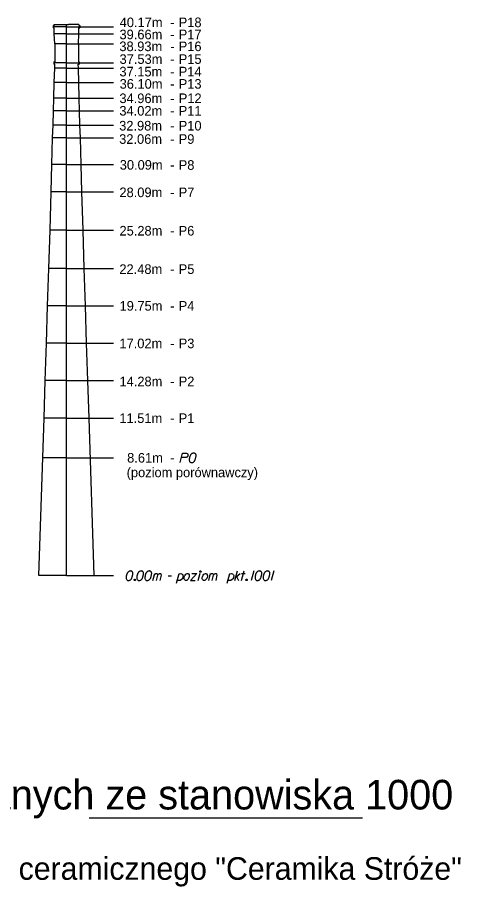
# Model space of a CAD drawing. Extents: x 138 to 264, y -75 to 121.
# Drawn here: x 182.42 to 189.53, y 85.34 to 99.29 of the extents above; entities that cross this region are included whole.
import ezdxf

# ---------------------------------------------------------------- set-up
doc = ezdxf.new("R2010")
doc.units = 0
doc.layers.add('Opisy', color=7, linetype='Continuous')

msp = doc.modelspace()

# ---------------------------------------------------------------- linework, layer by layer
at = {"layer": 'Opisy'}
for p, q in [((182.991, 99.16), (182.991, 99.141)), ((183.008, 99.16), (182.991, 99.16)), ((183.204, 99.141), (182.991, 99.141)), ((182.991, 99.141), (182.991, 99.122)), ((183.008, 99.122), (182.991, 99.122)), ((183.008, 99.178), (183.008, 99.16)), ((183.008, 99.178), (183.234, 99.178)), ((183.008, 99.028), (183.008, 99.122)), ((183.204, 90.332), (183.204, 99.178)), ((183.204, 99.141), (183.957, 99.141)), ((183.4, 99.178), (183.234, 99.178)), ((183.4, 99.178), (183.4, 99.16)), ((183.4, 99.16), (183.417, 99.16)), ((183.4, 99.122), (183.417, 99.122)), ((183.4, 99.028), (183.4, 99.122)), ((183.417, 99.16), (183.417, 99.141)), ((183.417, 99.141), (183.417, 99.122)), ((183.204, 99.028), (183.008, 99.028)), ((183.014, 98.868), (183.008, 99.028)), ((183.204, 99.028), (183.957, 99.028)), ((183.394, 98.868), (183.4, 99.028)), ((183.204, 98.868), (183.014, 98.868)), ((183.014, 98.868), (183.014, 98.58)), ((183.204, 98.868), (183.957, 98.868)), ((183.394, 98.868), (183.394, 98.58)), ((183.001, 98.58), (183.001, 98.561)), ((183.001, 98.58), (183.014, 98.58)), ((183.204, 98.561), (183.001, 98.561)), ((183.001, 98.561), (183.001, 98.542)), ((183.016, 98.542), (183.001, 98.542)), ((183.014, 98.478), (183.016, 98.542)), ((183.204, 98.561), (183.957, 98.561)), ((183.394, 98.478), (183.392, 98.542)), ((183.392, 98.542), (183.407, 98.542)), ((183.407, 98.58), (183.394, 98.58)), ((183.407, 98.58), (183.407, 98.561)), ((183.407, 98.561), (183.407, 98.542)), ((183.008, 98.247), (183.014, 98.478)), ((183.204, 98.478), (183.014, 98.478)), ((183.204, 98.478), (183.957, 98.478)), ((183.4, 98.247), (183.394, 98.478)), ((183.001, 97.997), (183.008, 98.247)), ((183.204, 98.247), (183.008, 98.247)), ((183.204, 98.247), (183.957, 98.247)), ((183.407, 97.997), (183.4, 98.247)), ((182.994, 97.791), (183.001, 97.997)), ((183.204, 97.997), (183.001, 97.997)), ((183.204, 97.997), (183.957, 97.997)), ((183.413, 97.791), (183.407, 97.997)), ((182.989, 97.563), (182.994, 97.791)), ((183.204, 97.791), (182.994, 97.791)), ((183.204, 97.791), (183.957, 97.791)), ((183.419, 97.563), (183.413, 97.791)), ((182.981, 97.361), (182.989, 97.563)), ((183.204, 97.563), (182.989, 97.563)), ((183.204, 97.563), (183.957, 97.563)), ((183.426, 97.361), (183.419, 97.563)), ((182.969, 96.929), (182.981, 97.361)), ((183.204, 97.361), (182.981, 97.361)), ((183.204, 97.361), (183.957, 97.361)), ((183.438, 96.929), (183.426, 97.361)), ((182.956, 96.491), (182.969, 96.929)), ((183.204, 96.929), (182.969, 96.929)), ((183.204, 96.929), (183.957, 96.929)), ((183.452, 96.491), (183.438, 96.929)), ((182.939, 95.874), (182.956, 96.491)), ((183.204, 96.491), (182.956, 96.491)), ((183.204, 96.491), (183.957, 96.491)), ((183.469, 95.874), (183.452, 96.491)), ((182.919, 95.261), (182.939, 95.874)), ((183.204, 95.874), (182.939, 95.874)), ((183.204, 95.874), (183.957, 95.874)), ((183.489, 95.261), (183.469, 95.874)), ((182.9, 94.662), (182.919, 95.261)), ((183.204, 95.261), (182.919, 95.261)), ((183.204, 95.261), (183.957, 95.261)), ((183.508, 94.662), (183.489, 95.261)), ((182.882, 94.064), (182.9, 94.662)), ((183.204, 94.662), (182.9, 94.662)), ((183.204, 94.662), (183.957, 94.662)), ((183.526, 94.064), (183.508, 94.662)), ((182.863, 93.462), (182.882, 94.064)), ((183.204, 94.064), (182.882, 94.064)), ((183.204, 94.064), (183.957, 94.064)), ((183.545, 93.462), (183.526, 94.064)), ((182.843, 92.856), (182.863, 93.462)), ((183.204, 93.462), (182.863, 93.462)), ((183.204, 93.462), (183.957, 93.462)), ((183.565, 92.856), (183.545, 93.462)), ((182.761, 90.332), (182.843, 92.856)), ((183.204, 92.856), (182.843, 92.856)), ((183.204, 92.856), (183.957, 92.856)), ((183.647, 90.332), (183.565, 92.856)), ((183.204, 92.219), (182.822, 92.219)), ((183.204, 92.219), (183.957, 92.219)), ((183.204, 90.332), (182.761, 90.332)), ((183.204, 90.332), (183.957, 90.332)), ((183.569, 86.444), (187.953, 86.444))]:
    msp.add_line(p, q, dxfattribs=at)
for points in [[(185.026, 92.145), (185.067, 92.299), (185.12, 92.299), (185.127, 92.298), (185.13, 92.296), (185.138, 92.293), (185.143, 92.289), (185.146, 92.284), (185.15, 92.278), (185.152, 92.27), (185.154, 92.262), (185.152, 92.256), (185.151, 92.251), (185.149, 92.247), (185.146, 92.243), (185.143, 92.238), (185.138, 92.234), (185.134, 92.232), (185.128, 92.23), (185.122, 92.228), (185.049, 92.228)], [(185.247, 92.299), (185.245, 92.299), (185.237, 92.298), (185.232, 92.296), (185.229, 92.295), (185.223, 92.293), (185.215, 92.289), (185.209, 92.285), (185.203, 92.281), (185.2, 92.276), (185.196, 92.27), (185.192, 92.264), (185.189, 92.256), (185.186, 92.251), (185.184, 92.244), (185.18, 92.232), (185.177, 92.214), (185.174, 92.199), (185.174, 92.186), (185.175, 92.176), (185.18, 92.165), (185.184, 92.159), (185.19, 92.152), (185.197, 92.147), (185.201, 92.146), (185.208, 92.145), (185.214, 92.145), (185.224, 92.146), (185.232, 92.148), (185.239, 92.152), (185.247, 92.158), (185.251, 92.162), (185.256, 92.166), (185.259, 92.171), (185.262, 92.175), (185.264, 92.181), (185.265, 92.183), (185.268, 92.19), (185.27, 92.197), (185.272, 92.204), (185.274, 92.209), (185.275, 92.213), (185.276, 92.217), (185.279, 92.228), (185.28, 92.234), (185.281, 92.24), (185.282, 92.249), (185.283, 92.26), (185.283, 92.264), (185.282, 92.268), (185.281, 92.273), (185.277, 92.281), (185.274, 92.285), (185.27, 92.289), (185.265, 92.293), (185.26, 92.295), (185.257, 92.296), (185.253, 92.298), (185.247, 92.299)], [(184.233, 90.406), (184.231, 90.406), (184.223, 90.405), (184.219, 90.404), (184.215, 90.403), (184.209, 90.4), (184.202, 90.397), (184.196, 90.393), (184.189, 90.388), (184.186, 90.383), (184.182, 90.377), (184.179, 90.371), (184.175, 90.364), (184.172, 90.359), (184.17, 90.352), (184.166, 90.34), (184.163, 90.321), (184.16, 90.307), (184.16, 90.293), (184.162, 90.284), (184.166, 90.273), (184.17, 90.267), (184.176, 90.259), (184.183, 90.255), (184.187, 90.253), (184.194, 90.252), (184.2, 90.252), (184.21, 90.253), (184.219, 90.256), (184.225, 90.259), (184.233, 90.266), (184.237, 90.269), (184.242, 90.274), (184.245, 90.279), (184.248, 90.283), (184.25, 90.289), (184.251, 90.291), (184.254, 90.297), (184.256, 90.304), (184.259, 90.312), (184.26, 90.317), (184.261, 90.32), (184.262, 90.325), (184.265, 90.336), (184.266, 90.342), (184.267, 90.348), (184.268, 90.357), (184.27, 90.367), (184.27, 90.371), (184.268, 90.376), (184.267, 90.381), (184.263, 90.388), (184.26, 90.393), (184.256, 90.397), (184.251, 90.4), (184.246, 90.403), (184.243, 90.404), (184.239, 90.405), (184.233, 90.406)], [(184.404, 90.406), (184.402, 90.406), (184.395, 90.405), (184.39, 90.404), (184.386, 90.403), (184.38, 90.4), (184.373, 90.397), (184.367, 90.393), (184.361, 90.388), (184.357, 90.383), (184.353, 90.377), (184.35, 90.371), (184.346, 90.364), (184.344, 90.359), (184.341, 90.352), (184.338, 90.34), (184.334, 90.321), (184.331, 90.307), (184.331, 90.293), (184.333, 90.284), (184.338, 90.273), (184.341, 90.267), (184.347, 90.259), (184.355, 90.255), (184.358, 90.253), (184.365, 90.252), (184.372, 90.252), (184.381, 90.253), (184.39, 90.256), (184.396, 90.259), (184.404, 90.266), (184.408, 90.269), (184.413, 90.274), (184.416, 90.279), (184.419, 90.283), (184.421, 90.289), (184.422, 90.291), (184.425, 90.297), (184.427, 90.304), (184.43, 90.312), (184.431, 90.317), (184.432, 90.32), (184.433, 90.325), (184.436, 90.336), (184.437, 90.342), (184.438, 90.348), (184.439, 90.357), (184.441, 90.367), (184.441, 90.371), (184.439, 90.376), (184.438, 90.381), (184.435, 90.388), (184.431, 90.393), (184.427, 90.397), (184.422, 90.4), (184.418, 90.403), (184.414, 90.404), (184.41, 90.405), (184.404, 90.406)], [(184.534, 90.406), (184.532, 90.406), (184.524, 90.405), (184.52, 90.404), (184.516, 90.403), (184.51, 90.4), (184.503, 90.397), (184.497, 90.393), (184.49, 90.388), (184.487, 90.383), (184.483, 90.377), (184.48, 90.371), (184.476, 90.364), (184.473, 90.359), (184.471, 90.352), (184.467, 90.34), (184.464, 90.321), (184.461, 90.307), (184.461, 90.293), (184.463, 90.284), (184.467, 90.273), (184.471, 90.267), (184.477, 90.259), (184.484, 90.255), (184.488, 90.253), (184.495, 90.252), (184.501, 90.252), (184.511, 90.253), (184.52, 90.256), (184.526, 90.259), (184.534, 90.266), (184.538, 90.269), (184.543, 90.274), (184.546, 90.279), (184.549, 90.283), (184.551, 90.289), (184.552, 90.291), (184.555, 90.297), (184.557, 90.304), (184.56, 90.312), (184.561, 90.317), (184.562, 90.32), (184.563, 90.325), (184.566, 90.336), (184.567, 90.342), (184.568, 90.348), (184.569, 90.357), (184.571, 90.367), (184.571, 90.371), (184.569, 90.376), (184.568, 90.381), (184.565, 90.388), (184.561, 90.393), (184.557, 90.397), (184.552, 90.4), (184.548, 90.403), (184.544, 90.404), (184.54, 90.405), (184.534, 90.406)], [(184.591, 90.252), (184.619, 90.363)], [(184.612, 90.333), (184.618, 90.347), (184.624, 90.354), (184.631, 90.359), (184.639, 90.363), (184.643, 90.365), (184.651, 90.365), (184.653, 90.364), (184.658, 90.359), (184.663, 90.353), (184.666, 90.342), (184.668, 90.336), (184.674, 90.347), (184.681, 90.354), (184.688, 90.359), (184.696, 90.363), (184.702, 90.365), (184.708, 90.365), (184.713, 90.364), (184.716, 90.359), (184.72, 90.353), (184.724, 90.342), (184.725, 90.336), (184.704, 90.252)], [(184.647, 90.252), (184.668, 90.336)], [(184.834, 90.33), (184.886, 90.33)], [(184.969, 90.212), (185.01, 90.364)], [(185.006, 90.35), (185.019, 90.36), (185.037, 90.364), (185.051, 90.361), (185.061, 90.354), (185.068, 90.344), (185.073, 90.331), (185.074, 90.319), (185.072, 90.308), (185.068, 90.295), (185.059, 90.28), (185.047, 90.267), (185.028, 90.255), (185.013, 90.252), (184.998, 90.253), (184.982, 90.262)], [(185.142, 90.364), (185.151, 90.364), (185.161, 90.359), (185.17, 90.346), (185.172, 90.34), (185.173, 90.333), (185.173, 90.329), (185.173, 90.31), (185.169, 90.298), (185.163, 90.284), (185.156, 90.272), (185.144, 90.261), (185.133, 90.252), (185.115, 90.252), (185.107, 90.255), (185.1, 90.261), (185.096, 90.267), (185.091, 90.281), (185.091, 90.303), (185.094, 90.31), (185.099, 90.326), (185.104, 90.335), (185.106, 90.34), (185.118, 90.353), (185.13, 90.36), (185.142, 90.364)], [(185.215, 90.366), (185.294, 90.366), (185.193, 90.252), (185.271, 90.252)], [(185.315, 90.252), (185.346, 90.37)], [(185.349, 90.406), (185.355, 90.406), (185.358, 90.404), (185.362, 90.399), (185.362, 90.393), (185.358, 90.388), (185.355, 90.386), (185.349, 90.386), (185.345, 90.388), (185.341, 90.393), (185.341, 90.399), (185.345, 90.404), (185.349, 90.406)], [(185.434, 90.364), (185.442, 90.364), (185.452, 90.359), (185.462, 90.346), (185.463, 90.34), (185.464, 90.333), (185.464, 90.329), (185.464, 90.31), (185.46, 90.298), (185.454, 90.284), (185.447, 90.272), (185.435, 90.261), (185.424, 90.252), (185.406, 90.252), (185.399, 90.255), (185.391, 90.261), (185.388, 90.267), (185.383, 90.281), (185.383, 90.303), (185.385, 90.31), (185.39, 90.326), (185.395, 90.335), (185.397, 90.34), (185.409, 90.353), (185.422, 90.36), (185.434, 90.364)], [(185.485, 90.252), (185.513, 90.363)], [(185.505, 90.333), (185.511, 90.347), (185.517, 90.354), (185.525, 90.359), (185.532, 90.363), (185.537, 90.365), (185.544, 90.365), (185.547, 90.364), (185.551, 90.359), (185.556, 90.353), (185.56, 90.342), (185.561, 90.336), (185.567, 90.347), (185.575, 90.354), (185.582, 90.359), (185.589, 90.363), (185.595, 90.365), (185.601, 90.365), (185.606, 90.364), (185.61, 90.359), (185.613, 90.353), (185.617, 90.342), (185.618, 90.336), (185.598, 90.252)], [(185.541, 90.252), (185.561, 90.336)], [(185.782, 90.212), (185.823, 90.364)], [(185.82, 90.35), (185.832, 90.36), (185.85, 90.364), (185.865, 90.361), (185.874, 90.354), (185.882, 90.344), (185.887, 90.331), (185.888, 90.319), (185.885, 90.308), (185.882, 90.295), (185.872, 90.28), (185.86, 90.267), (185.842, 90.255), (185.826, 90.252), (185.811, 90.253), (185.795, 90.262)], [(185.905, 90.252), (185.946, 90.406)], [(185.919, 90.307), (185.992, 90.367)], [(185.934, 90.319), (185.965, 90.252)], [(186.013, 90.252), (186.053, 90.406)], [(186.013, 90.364), (186.071, 90.364)], [(186.208, 90.406), (186.167, 90.252)], [(186.302, 90.406), (186.299, 90.406), (186.292, 90.405), (186.287, 90.404), (186.283, 90.403), (186.277, 90.4), (186.27, 90.397), (186.264, 90.393), (186.258, 90.388), (186.254, 90.383), (186.251, 90.377), (186.247, 90.371), (186.243, 90.364), (186.241, 90.359), (186.238, 90.352), (186.235, 90.34), (186.231, 90.321), (186.229, 90.307), (186.229, 90.293), (186.23, 90.284), (186.235, 90.273), (186.238, 90.267), (186.245, 90.259), (186.252, 90.255), (186.255, 90.253), (186.263, 90.252), (186.269, 90.252), (186.279, 90.253), (186.287, 90.256), (186.293, 90.259), (186.302, 90.266), (186.305, 90.269), (186.31, 90.274), (186.314, 90.279), (186.316, 90.283), (186.319, 90.289), (186.32, 90.291), (186.322, 90.297), (186.325, 90.304), (186.327, 90.312), (186.328, 90.317), (186.33, 90.32), (186.331, 90.325), (186.333, 90.336), (186.334, 90.342), (186.336, 90.348), (186.337, 90.357), (186.338, 90.367), (186.338, 90.371), (186.337, 90.376), (186.336, 90.381), (186.332, 90.388), (186.328, 90.393), (186.325, 90.397), (186.32, 90.4), (186.315, 90.403), (186.311, 90.404), (186.308, 90.405), (186.302, 90.406)], [(186.431, 90.406), (186.429, 90.406), (186.422, 90.405), (186.417, 90.404), (186.413, 90.403), (186.407, 90.4), (186.4, 90.397), (186.394, 90.393), (186.388, 90.388), (186.384, 90.383), (186.38, 90.377), (186.377, 90.371), (186.373, 90.364), (186.371, 90.359), (186.368, 90.352), (186.365, 90.34), (186.361, 90.321), (186.359, 90.307), (186.359, 90.293), (186.36, 90.284), (186.365, 90.273), (186.368, 90.267), (186.374, 90.259), (186.382, 90.255), (186.385, 90.253), (186.393, 90.252), (186.399, 90.252), (186.408, 90.253), (186.417, 90.256), (186.423, 90.259), (186.431, 90.266), (186.435, 90.269), (186.44, 90.274), (186.444, 90.279), (186.446, 90.283), (186.448, 90.289), (186.45, 90.291), (186.452, 90.297), (186.455, 90.304), (186.457, 90.312), (186.458, 90.317), (186.459, 90.32), (186.461, 90.325), (186.463, 90.336), (186.464, 90.342), (186.465, 90.348), (186.467, 90.357), (186.468, 90.367), (186.468, 90.371), (186.467, 90.376), (186.465, 90.381), (186.462, 90.388), (186.458, 90.393), (186.455, 90.397), (186.45, 90.4), (186.445, 90.403), (186.441, 90.404), (186.438, 90.405), (186.431, 90.406)], [(186.53, 90.406), (186.489, 90.252)], [(184.297, 90.273), (184.304, 90.273), (184.307, 90.27), (184.311, 90.266), (184.311, 90.259), (184.307, 90.255), (184.304, 90.252), (184.297, 90.252), (184.294, 90.255), (184.29, 90.259), (184.29, 90.266), (184.294, 90.27), (184.297, 90.273)], [(186.092, 90.273), (186.098, 90.273), (186.101, 90.27), (186.105, 90.266), (186.105, 90.259), (186.101, 90.255), (186.098, 90.252), (186.092, 90.252), (186.088, 90.255), (186.084, 90.259), (186.084, 90.266), (186.088, 90.27), (186.092, 90.273)]]:
    msp.add_lwpolyline(points, dxfattribs=at)

# ---------------------------------------------------------------- texts
for s, height, p in [('40.17m', 0.1542, (184.057, 99.135)), ('P18', 0.1542, (185.004, 99.135)), ('39.66m', 0.1542, (184.054, 98.941)), ('-', 0.154, (184.867, 99.135)), ('P17', 0.1542, (185.004, 98.941)), ('-', 0.154, (184.868, 98.941)), ('38.93m', 0.1542, (184.052, 98.75)), ('-', 0.154, (184.871, 98.75)), ('P16', 0.1542, (185.004, 98.75)), ('37.53m', 0.1542, (184.055, 98.545)), ('P15', 0.1542, (185.004, 98.545)), ('-', 0.154, (184.867, 98.545)), ('37.15m', 0.1542, (184.053, 98.344)), ('-', 0.154, (184.867, 98.344)), ('P14', 0.1542, (185.004, 98.344)), ('36.10m', 0.1542, (184.056, 98.147)), ('P13', 0.1542, (185.004, 98.147)), ('-', 0.154, (184.868, 98.147)), ('34.96m', 0.1542, (184.053, 97.916)), ('-', 0.154, (184.868, 97.916)), ('P12', 0.1542, (185.005, 97.916)), ('34.02m', 0.1542, (184.052, 97.715)), ('P11', 0.1542, (185.004, 97.715)), ('-', 0.154, (184.868, 97.715)), ('32.98m', 0.1542, (184.049, 97.476)), ('-', 0.154, (184.868, 97.476)), ('P10', 0.1542, (185.004, 97.476)), ('32.06m', 0.1542, (184.049, 97.262)), ('P9', 0.1542, (185.004, 97.262)), ('-', 0.154, (184.868, 97.262)), ('30.09m', 0.1542, (184.058, 96.847)), ('P8', 0.1542, (185.004, 96.845)), ('-', 0.154, (184.868, 96.847)), ('28.09m', 0.1542, (184.053, 96.406)), ('P7', 0.1542, (185.004, 96.406)), ('-', 0.154, (184.868, 96.406)), ('25.28m', 0.1542, (184.054, 95.79)), ('P6', 0.1542, (185.003, 95.79)), ('-', 0.154, (184.867, 95.79)), ('22.48m', 0.1542, (184.052, 95.174)), ('P5', 0.1542, (185.004, 95.174)), ('-', 0.154, (184.867, 95.174)), ('19.75m', 0.1542, (184.055, 94.584)), ('-', 0.154, (184.867, 94.584)), ('P4', 0.1542, (185.004, 94.584)), ('17.02m', 0.1542, (184.053, 93.981)), ('-', 0.154, (184.867, 93.981)), ('P3', 0.1542, (185.004, 93.981)), ('14.28m', 0.1542, (184.054, 93.371)), ('P2', 0.1542, (185.004, 93.371)), ('-', 0.154, (184.868, 93.371)), ('11.51m', 0.1542, (184.052, 92.781)), ('P1', 0.1542, (185.004, 92.781)), ('-', 0.154, (184.867, 92.781)), ('8.61m', 0.1542, (184.177, 92.145)), ('-', 0.154, (184.867, 92.145)), ('(poziom porównawczy)', 0.15416, (184.169, 91.911)), ('Wykres wychyleń osi komina obserwowanych ze stanowiska 1000', 0.47516, (170.798, 86.577)), ('Badanie pionowości i prostoliniowości komina zakładu ceramicznego "Ceramika Stróże"', 0.36281, (170.678, 85.448))]:
    msp.add_text(s, height=height, dxfattribs=at).set_placement(p)

doc.saveas('drawing.dxf')
